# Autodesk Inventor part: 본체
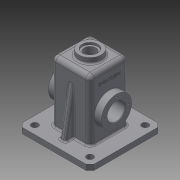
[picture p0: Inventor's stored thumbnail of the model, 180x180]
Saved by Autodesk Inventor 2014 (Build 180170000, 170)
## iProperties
Created: 2016-02
Part Number: 본체
Material: 일반
Document SubType Name: Modeling
Designer: aapexcom
Density: 1 g/cm^3
Appearance: 기본값
Author: aapexcom
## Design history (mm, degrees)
sketch "스케치1"
  geometry: L1 (-57.935, 65)-(57.935, 65); L2 (65, 57.935)-(65, -57.935); L3 (57.935, -65)-(-57.935, -65); L4 (-65, -57.935)-(-65, 57.935); L5 (-65, 65)-(65, -65); L6 (65, 65)-(-65, -65); L7 (-82.011, 0)-(89.869, 0); L8 (-57.935, 65)-(-65.006, 57.929); L9 (-57.935, -65)-(-65.006, -57.929); L10 (0, 65)-(0, -95.925); L11 (57.935, 65)-(65.006, 57.929); L12 (57.935, -65)-(65.006, -57.929); 1 further point
  constraints: 24 end point, 6 symmetric about line, 4 parallel, 4 perpendicular, 4 point on line, 3 midpoint, 1 horizontal
  dimensions: "d0" = 130 distance of L5.start L6.start; "d1" = 130 distance of L6.end L5.start; "d51" = 10 distance of L1.start L8.end; "d52" = 86.92792 distance between parallel lines of L8 L6; "d53" = 65 distance between parallel lines of L7 L1; "d54" = 24.86887 distance from line of L7.end L2; "d55" = 147.01132 distance from line of L7.start L2; "d56" = 65 distance between parallel lines of L10 L2; "d57" = 130 distance between parallel lines of L4 L2; "d58" = 154.75749 distance from line of L10.end L11; "d59" = 86.92792 distance between parallel lines of L11 L5; "d60" = 173.85585 distance between parallel lines of L11 L9; "d61" = 0 distance from line of L6.start L2; "d62" = 0 distance from line of L5.end L2
extrude "돌출1" new body sketch "스케치1" distance "d2" = 10; taper "d3" = 0 deg
sketch "스케치2"
  geometry: L1 (-35, 35)-(35, 35); L2 (35, 35)-(35, -35); L3 (35, -35)-(-35, -35); L4 (-35, -35)-(-35, 35); L5 (-35, 35)-(35, -35); L6 (35, 35)-(-35, -35); 1 further point
  constraints: 12 end point, 2 midpoint, 2 parallel, 1 horizontal, 1 perpendicular
  dimensions: "d4" = 70 distance of L1.start L1.end; "d5" = 70 distance of L3.end L1.start
extrude "돌출2" join sketch "스케치2" distance "d6" = 110; taper "d7" = 0 deg
fillet "모깎기1" dims "d8" = 8
sketch "스케치3"
  geometry: C1 r 20 at (0, 0); 1 further point
  constraints: 1 centre point, 1 coincident
  dimensions: "d9" = 40 diameter of C1
extrude "돌출3" join sketch "스케치3" distance "d10" = 10; taper "d11" = 0 deg
sketch "스케치4"
  geometry: C1 r 20 at (0, 0) reference; C2 r 14 at (0, 0)
  constraints: 1 centre point, 1 coincident
  dimensions: "d12" = 28 diameter of C2
extrude "돌출4" cut sketch "스케치4" distance "d13" = 4; taper "d14" = 0 deg
sketch "스케치5"
  geometry: L1 (-30, 30)-(30, 30); L2 (30, 30)-(30, -30); L3 (30, -30)-(-30, -30); L4 (-30, -30)-(-30, 30); L5 (-30, 30)-(30, -30); L6 (30, 30)-(-30, -30); 1 further point
  constraints: 12 end point, 2 midpoint, 2 parallel, 1 horizontal, 1 perpendicular
  dimensions: "d15" = 60 distance of L1.start L1.end; "d16" = 60 distance of L3.end L1.start
extrude "돌출5" cut sketch "스케치5" distance "d17" = 115; taper "d18" = 0 deg
sketch "스케치6"
  geometry: C1 r 14 at (0, 0) reference; C2 r 10.5 at (0, 0)
  constraints: 1 centre point, 1 coincident
  dimensions: "d19" = 21 diameter of C2
extrude "돌출6" cut sketch "스케치6" stored distance "d20" = 115; taper "d21" = 0 deg
node "작업 평면1"
sketch "스케치7"
  geometry: L1 (0, 60)-(0, 0) reference; C1 r 27.5 at (-55, 30); 2 further points
  constraints: 1 centre point, 1 horizontal alignment, 1 midpoint
  dimensions: "d23" = 55 distance from line of L1 C1.centre; "d24" = 55 diameter of C1
extrude "돌출7" join sketch "스케치7" stored distance "d25" = 115; taper "d26" = 45 deg
sketch "스케치10"
  geometry: L1 (-10, 57)-(-10, -3) reference; C1 r 27.5 at (45, 27); 1 further point
  constraints: 1 centre point, 1 horizontal alignment
  dimensions: "d32" = 55 diameter of C1; "d33" = 55 distance from line of C1.centre L1
extrude "돌출9" join sketch "스케치10" distance "d34" = 13; taper "d35" = 0 deg
sketch "스케치11"
  geometry: C1 r 27.5 at (0, 0) reference; C2 r 16 at (0, 0); 1 further point
  constraints: 1 centre point, 1 coincident
  dimensions: "d36" = 32 diameter of C2
extrude "돌출10" cut sketch "스케치11" stored distance "d37" = 13; taper "d38" = 0 deg
sketch "스케치12" dims "d39" = 45
  geometry: L1 (0, 0)-(0, 22.5); C1 r 27.5 at (0, 0) reference; 1 further point
  constraints: 2 end point, 1 coincident, 1 vertical, 1 vertical alignment, 2 other
hole "구멍1" sketch "스케치12" at (0, 22.5) diameter "d40" = 3.242; stored, may be unused: countersink angle "d44" = 90 deg, drill point angle "d46" = 118 deg; dims "d41" = 8, "d42" = 4, "d43" = 2, "d45" = 10
sketch "스케치13"
  geometry: L1 (65, 57.935)-(57.935, 65) reference; L2 (57.935, 65)-(-57.935, 65) reference; L3 (27, -35)-(-27, -35) reference; L4 (-27, 35)-(27, 35) reference; L5 (-82.924, 0)-(100.555, 0); C1 r 6 at (-50, 50); C2 r 6 at (50, 50); C3 r 6 at (-50, -50); C4 r 6 at (50, -50); 1 further point
  constraints: 4 centre point, 2 end point, 2 symmetric about line, 1 parallel, 2 other
  dimensions: "d63" = 50 horizontal distance of C1.centre point (0, 0); "d64" = 15 distance from line of C1.centre L2; "d65" = 12 diameter of C1; "d66" = 50 horizontal distance of C2.centre point (0, 0); "d67" = 15 distance from line of C2.centre L2; "d68" = 12 diameter of C2; "d69" = 35 distance between parallel lines of L3 L5; "d70" = 15.82483 distance from line of L5.end L1; "d71" = 145.56421 distance from line of L5.start L1
extrude "돌출11" cut sketch "스케치13" distance "d72" = 10; taper "d73" = 0 deg
sketch "스케치14"
  geometry: L1 (57.935, 10)-(-57.935, 10) reference; L2 (-35, 10)-(-35, 112) reference; L3 (35, 112)-(35, 10) reference; L4 (35, 95.069)-(50, 10); L5 (65, 0)-(65, 10) reference; L6 (0, -22.061)-(0, 146.662); L7 (-35, 95.069)-(-50, 10); L8 (-35, 95.069)-(-35, 10); L9 (-50, 10)-(-35, 10); 3 further points
  constraints: 10 end point, 2 point on line, 2 symmetric about line, 1 collinear, 1 parallel
  dimensions: "d74" = 10 deg angle of L5 L4; "d75" = 15 distance from line of L4.end L5; "d76" = 35 distance between parallel lines of L2 L6; "d77" = 136.66209 distance from line of L6.end L1; "d78" = 32.06099 distance from line of L6.start L1
extrude "돌출12" join sketch "스케치14" stored distance "d79" = 10; taper "d80" = 0 deg
node "작업 평면2"
sketch "스케치15"
  geometry: L1 (20, 130)-(-20, 130) reference; L2 (35, 10)-(35, 112) reference; 3 further points
  constraints: 1 other
  dimensions: "d82" = 30 distance from line of point (0, 100) L1; "d83" = 35 distance from line of L2 point (0, 100)
feature "엠보싱1" sketch "스케치15" dims "d0" = 130, "d1" = 130, "d51" = 10, "d52" = 86.92792, "d53" = 65, "d54" = 24.86887, "d55" = 147.01132, "d56" = 65, "d57" = 130, "d58" = 154.75749, "d59" = 86.92792, "d60" = 173.85585, "d61" = 0, "d62" = 0, "d84" = 0.5, "d85" = 0
fillet "모깎기2" dims "d86" = 3
fillet "모깎기3" dims "d87" = 3
chamfer "모따기1" distance "d88" = 1; stored, may be unused: second distance "d89" = 2, angle "d90" = 45 deg
fillet "모깎기4" dims "d91" = 0.5
node "솔리드1"
pattern_circular "원형 패턴1" dims angle "d48" = 360 deg
mirror "대칭1"
mirror "대칭2"
other parameters: "d22" = 7, "d81" = 67.5
